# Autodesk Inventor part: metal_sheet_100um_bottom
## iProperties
Company: Mc Gill University
Created: 2007-11
Part Number: metal_sheet_100um_bottom
Document SubType Name: Modeling
Designer: Administrateur
Material: Stainless Steel
Author: Administrateur
Title: Metal sheet bottom - thinckness 100 micrometers
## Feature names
1. Extrusion1
2. Extrusion2
3. Fillet1
